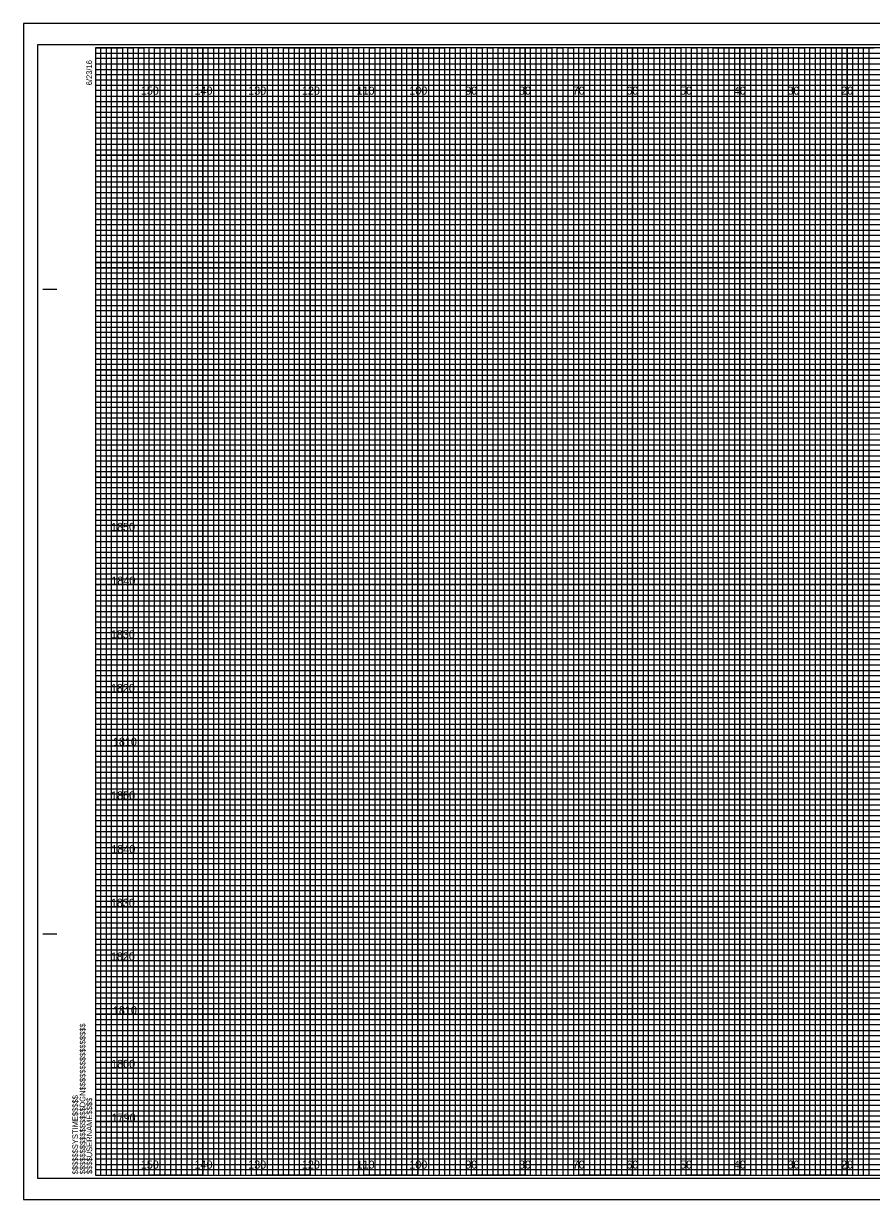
# Model space of a CAD drawing. Extents: x -13 to 323, y -5 to 874.
# Drawn here: x -13.4 to 144.5, y 655.5 to 874.5 of the extents above; entities that cross this region are included whole.
import ezdxf

# ---------------------------------------------------------------- set-up
doc = ezdxf.new("R2010")
doc.units = 0
for name, color, linetype in [('Prop XS Earthwork Shape', 7, 'Continuous'), ('Raster_Level_0', 7, 'Continuous'), ('Scratch_Level_3', 7, 'Continuous'), ('Sheet Cross Section CELL', 7, 'Continuous'), ('Sheet Cross Section Grid Middle CELL', 7, 'Continuous'), ('Sheet Cross Section Grid Minor 1 CELL', 7, 'Continuous'), ('Sheet Cross Section Grid Minor 2 CELL', 7, 'Continuous'), ('Sheet Cutting Line CELL', 7, 'Continuous'), ('Sheet DOT Grid CELL', 7, 'Continuous'), ('Sheet Plot Border Inside CELL', 7, 'Continuous'), ('Sheet Plot Border Outside CELL', 7, 'Continuous')]:
    doc.layers.add(name, color=color, linetype=linetype)

msp = doc.modelspace()

# ---------------------------------------------------------------- linework, layer by layer
at = {"layer": 'Prop XS Earthwork Shape'}
for p, q in [((10, 870), (0, 870)), ((10, 660), (10, 870)), ((30, 870), (20, 870)), ((20, 870), (20, 660)), ((30, 660), (30, 870)), ((50, 870), (40, 870)), ((40, 870), (40, 660)), ((50, 660), (50, 870)), ((70, 870), (60, 870)), ((60, 870), (60, 660)), ((70, 660), (70, 870)), ((90, 870), (80, 870)), ((80, 870), (80, 660)), ((90, 660), (90, 870)), ((110, 870), (100, 870)), ((100, 870), (100, 660)), ((110, 660), (110, 870)), ((130, 870), (120, 870)), ((120, 870), (120, 660)), ((130, 660), (130, 870)), ((150, 870), (140, 870)), ((140, 870), (140, 660)), ((20, 660), (10, 660)), ((40, 660), (30, 660)), ((60, 660), (50, 660)), ((80, 660), (70, 660)), ((100, 660), (90, 660)), ((120, 660), (110, 660)), ((140, 660), (130, 660))]:
    msp.add_line(p, q, dxfattribs=at)
for points in [[(0, 860), (320, 860), (320, 850), (0, 850)], [(0, 840), (320, 840), (320, 830), (0, 830)], [(0, 820), (320, 820), (320, 810), (0, 810)], [(0, 800), (320, 800), (320, 790), (0, 790)], [(0, 780), (320, 780), (320, 770), (0, 770)], [(0, 760), (320, 760), (320, 750), (0, 750)], [(0, 740), (320, 740), (320, 730), (0, 730)], [(0, 720), (320, 720), (320, 710), (0, 710)], [(0, 700), (320, 700), (320, 690), (0, 690)], [(0, 680), (320, 680), (320, 670), (0, 670)]]:
    msp.add_lwpolyline(points, dxfattribs=at)
at = {"layer": 'Sheet Cross Section CELL'}
for p, q in [((-9.8, 825), (-7.3, 825)), ((-9.7, 825), (-7.2, 825)), ((-9.8, 705), (-7.3, 705)), ((-9.7, 705), (-7.2, 705)), ((0, 660), (0, 660)), ((0, 660), (0, 660)), ((0, 660), (0, 660)), ((0, 660), (0, 660)), ((0, 660), (0, 660)), ((0, 660), (0, 660)), ((0, 660), (0, 660))]:
    msp.add_line(p, q, dxfattribs=at)
msp.add_lwpolyline([(320, 870), (0, 870), (0, 660), (320, 660)], close=True, dxfattribs=at)
at = {"layer": 'Sheet Cross Section Grid Middle CELL'}
for points in [[(0, 870), (5, 870), (5, 660), (15, 660), (15, 870), (25, 870), (25, 660), (35, 660), (35, 870), (45, 870), (45, 660), (55, 660), (55, 870), (65, 870), (65, 660), (75, 660), (75, 870), (85, 870), (85, 660), (95, 660), (95, 870), (105, 870), (105, 660), (115, 660), (115, 870), (125, 870), (125, 660), (135, 660), (135, 870), (145, 870)], [(0, 865), (275, 865)], [(0, 845), (320, 845), (320, 855), (0, 855)], [(0, 825), (320, 825), (320, 835), (0, 835)], [(0, 805), (320, 805), (320, 815), (0, 815)], [(0, 785), (320, 785), (320, 795), (0, 795)], [(0, 765), (320, 765), (320, 775), (0, 775)], [(0, 745), (320, 745), (320, 755), (0, 755)], [(0, 725), (320, 725), (320, 735), (0, 735)], [(0, 705), (320, 705), (320, 715), (0, 715)], [(0, 685), (320, 685), (320, 695), (0, 695)], [(0, 665), (320, 665), (320, 675), (0, 675)]]:
    msp.add_lwpolyline(points, dxfattribs=at)
at = {"layer": 'Sheet Cross Section Grid Minor 1 CELL'}
for p, q in [((0, 869), (260, 869)), ((260, 867.98), (0, 867.98)), ((0, 867.98), (0, 867)), ((0, 867), (260, 867)), ((260, 865.89), (0, 865.89)), ((0, 865.89), (0, 864)), ((0, 864), (320, 864))]:
    msp.add_line(p, q, dxfattribs=at)
for points in [[(0, 863), (270, 863), (320, 863), (320, 862), (0, 862)], [(0, 861), (320, 861), (320, 859), (0, 859)], [(0, 858), (320, 858), (320, 857), (0, 856.98)], [(0, 856), (320, 856), (320, 854), (0, 854)], [(0, 853), (320, 853), (320, 852), (0, 852)], [(0, 851), (320, 851), (320, 849), (0, 849)], [(0, 848), (320, 848), (320, 847), (0, 847)], [(0, 846), (320, 846), (320, 844), (0, 844)], [(0, 843), (320, 843), (320, 842), (0, 842)], [(0, 841), (320, 841), (320, 839), (0, 839)], [(0, 838), (320, 838), (320, 837), (0, 837)], [(0, 836), (320, 836), (320, 833.95), (320, 833), (320, 832), (0, 832)], [(0, 834), (320, 834), (320, 833), (0, 833)], [(0, 831), (320, 831), (320, 829), (0, 829.03)], [(0, 829.03), (320, 829), (320, 828), (0, 828)], [(0, 827), (320, 827), (320, 826), (0, 826)], [(0, 824), (320, 824), (320, 823), (0, 823)], [(0, 822), (320, 822), (320, 821), (0, 821)], [(-0.07, 818.89), (320, 818.89), (320, 817.88), (-0.07, 817.88)], [(0, 817), (320, 817), (320, 816), (0, 816)], [(0, 814), (320, 814), (320, 813), (0, 813)], [(0, 812), (320, 812), (320, 811), (0, 811)], [(0, 809), (320, 809), (320, 808), (0, 808)], [(0, 807), (320, 807), (320, 806), (0, 806)], [(0, 804), (320, 804), (320, 803), (0, 803)], [(0, 802), (320, 802), (320, 801), (0, 801)], [(0, 799), (320, 799), (319.99, 797.98), (0, 798)], [(0, 797), (320, 797), (320, 796), (0, 796)], [(0, 794), (320, 794), (320, 793), (0, 793)], [(0, 792), (320, 792), (320, 791), (0, 791)], [(0, 789), (320, 789), (320, 788), (0, 788)], [(0, 787), (320, 787), (320, 786), (0, 786)], [(0, 784), (320, 784), (320, 783), (0, 783)], [(0, 782), (320, 782), (320, 781), (0, 781)], [(0, 779), (320, 779), (320, 778), (0, 778)], [(0, 776.99), (320.07, 776.91), (320, 776), (0, 776)], [(0, 774), (320, 774), (320, 773), (0, 773)], [(0, 772), (320, 772), (320, 771), (0, 771)], [(0, 769), (320, 769), (320, 768), (0, 768)], [(0, 767), (320, 767), (320, 766), (0, 766)], [(0, 764), (320, 764), (320, 763), (0, 763)], [(0, 762), (320, 762), (320, 761), (0, 761)], [(0, 759), (320, 759), (320, 758), (0, 758)], [(0, 757), (320, 757), (320, 756), (0, 756)], [(0, 754), (320, 754), (320, 753), (0, 753)], [(0, 752), (320, 752), (320, 751), (0, 751)], [(0, 749), (320, 749), (320, 748), (0, 748)], [(0, 747), (320, 747), (320, 746), (0, 746)], [(0, 744), (320, 744), (320, 743), (0, 743)], [(0, 742), (320, 742), (320, 741), (0, 741)], [(0, 739), (320, 739), (319.99, 737.98), (0, 738)], [(0, 737), (320, 737), (320, 736), (0, 736)], [(0, 734), (320, 734), (320, 733), (0, 733)], [(0, 732), (320, 732), (320, 731), (0, 731)], [(0, 729), (320, 729), (320, 728), (0, 728)], [(0, 727), (320, 727), (320, 726), (0, 726)], [(0, 724), (320, 724), (320, 723), (0, 723)], [(0, 722), (320, 722), (320, 721), (0, 721)], [(0, 719), (320, 719), (320, 718), (0, 718)], [(0, 716.99), (320.07, 716.91), (320, 716), (0, 716)], [(0, 714), (320, 714), (320, 713), (0, 713)], [(0, 712), (320, 712), (320, 711), (0, 711)], [(0, 709), (320, 709), (320, 708), (0, 708)], [(0, 707), (320, 707), (320, 706), (0, 706)], [(0, 704), (320, 704), (320, 703), (0, 703)], [(0, 702), (320, 702), (320, 701), (0, 701)], [(0, 699), (320, 699), (320, 698), (0, 698)], [(0, 697), (320, 697), (320, 696), (0, 696)], [(0, 694), (320, 694), (320, 693), (0, 693)], [(0, 692), (320, 692), (320, 691), (0, 691)], [(0, 689), (320, 689), (320, 688), (0, 688)], [(0, 687), (320, 687), (320, 686), (0, 686)], [(0, 684), (320, 684), (320, 683), (0, 683)], [(0, 682), (320, 682), (320, 681), (0, 681)], [(0, 679), (320, 679), (320, 678), (0, 678)], [(0, 677), (320, 677), (320, 676), (0, 676)], [(0, 674), (320, 674), (320, 673), (0, 673)], [(0, 672), (320, 672), (320, 671), (0, 671)], [(0, 669), (320, 669), (320, 668), (0, 668)], [(0, 667), (320, 667), (320, 666), (0, 666)], [(0, 664), (320, 664), (320, 663), (0, 663)], [(0, 662), (320, 662), (320, 661), (0, 661)]]:
    msp.add_lwpolyline(points, dxfattribs=at)
at = {"layer": 'Sheet Cross Section Grid Minor 2 CELL'}
for points in [[(0, 660), (1, 660), (1, 870), (2, 870), (2, 660)], [(2, 660), (3, 660), (3, 870), (4, 870), (4, 660)], [(5, 660), (6, 660), (6, 870), (7, 870), (7, 660)], [(7, 660), (8, 660), (8, 870), (9, 870), (9, 660)], [(10, 660), (11, 660), (11, 870), (12, 870), (12, 660)], [(12, 660), (13, 660), (13, 870), (14, 870), (14, 660)], [(15, 660), (16, 660), (16, 870), (17, 870), (17, 660)], [(17, 660), (18, 660), (18, 870), (19, 870), (19, 660)], [(20, 660), (21, 660), (21, 870), (22, 870), (22, 660)], [(22, 660), (23, 660), (23, 870), (24, 870), (24, 660)], [(25, 660), (26, 660), (26, 870), (27, 870), (27, 660)], [(27, 660), (28, 660), (28, 870), (29, 870), (29, 660)], [(30, 660), (31, 660), (31, 870), (32, 870), (32, 660)], [(32, 660), (33, 660), (33, 870), (34, 870), (34, 660)], [(35, 660), (36, 660), (36, 870), (37, 870), (37, 660)], [(37, 660), (38, 660), (38, 870), (39, 870), (39, 660)], [(40, 660), (41, 660), (41, 870), (42, 870), (42, 660)], [(42, 660), (43, 660), (43, 870), (44, 870), (44, 660)], [(45, 660), (46, 660), (46, 870), (47, 870), (47, 660)], [(47, 660), (48, 660), (48, 870), (49, 870), (49, 660)], [(50, 660), (51, 660), (51, 870), (52, 870), (52, 660)], [(52, 660), (53, 660), (53, 870), (54, 870), (54, 660)], [(55, 660), (56, 660), (56, 870), (57, 870), (57, 660)], [(57, 660), (58, 660), (58, 870), (59, 870), (59, 660)], [(60, 660), (61, 660), (61, 870), (62, 870), (62, 660)], [(62, 660), (63, 660), (63, 870), (64, 870), (64, 660)], [(65, 660), (66, 660), (66, 870), (67, 870), (67, 660)], [(67, 660), (68, 660), (68, 870), (69, 870), (69, 660)], [(70, 660), (71, 660), (71, 870), (72, 870), (72, 660)], [(72, 660), (73, 660), (73, 870), (74, 870), (74, 660)], [(75, 660), (76, 660), (76, 870), (77, 870), (77, 660)], [(77, 660), (78, 660), (78, 870), (79, 870), (79, 660)], [(80, 660), (81, 660), (81, 870), (82, 870), (82, 660)], [(82, 660), (83, 660), (83, 870), (84, 870), (84, 660)], [(85, 660), (86, 660), (86, 870), (87, 870), (87, 660)], [(87, 660), (88, 660), (88, 870), (89, 870), (89, 660)], [(90, 660), (91, 660), (91, 870), (92, 870), (92, 660)], [(92, 660), (93, 660), (93, 870), (94, 870), (94, 660)], [(95, 660), (96, 660), (96, 870), (97, 870), (97, 660)], [(97, 660), (98, 660), (98, 870), (99, 870), (99, 660)], [(100, 660), (101, 660), (101, 870), (102, 870), (102, 660)], [(102, 660), (103, 660), (103, 870), (104, 870), (104, 660)], [(105, 660), (106, 660), (106, 870), (107, 870), (107, 660)], [(107, 660), (108, 660), (108, 870), (109, 870), (109, 660)], [(110, 660), (111, 660), (111, 870), (112, 870), (112, 660)], [(112, 660), (113, 660), (113, 870), (114, 870), (114, 660)], [(115, 660), (116, 660), (116, 870), (117, 870), (117, 660)], [(117, 660), (118, 660), (118, 870), (119, 870), (119, 660)], [(120, 660), (121, 660), (121, 870), (122, 870), (122, 660)], [(122, 660), (123, 660), (123, 870), (124, 870), (124, 660)], [(125, 660), (126, 660), (126, 870), (127, 870), (127, 660)], [(127, 660), (128, 660), (128, 870), (129, 870), (129, 660)], [(130, 660), (131, 660), (131, 870), (132, 870), (132, 660)], [(132, 660), (133, 660), (133, 870), (134, 870), (134, 660)], [(135, 660), (136, 660), (136, 870), (137, 870), (137, 660)], [(137, 660), (138, 660), (138, 870), (139, 870), (139, 660)], [(140, 660), (141, 660), (141, 870), (142, 870), (142, 660)], [(142, 660), (143, 660), (143, 870), (144, 870), (144, 660)]]:
    msp.add_lwpolyline(points, dxfattribs=at)
at = {"layer": 'Sheet Cutting Line CELL'}
for p, q in [((323.3, 874.5), (-13.4, 874.5)), ((-13.4, 874.5), (-13.4, 655.5)), ((-13.4, 655.5), (323.3, 655.5))]:
    msp.add_line(p, q, dxfattribs=at)
at = {"layer": 'Sheet DOT Grid CELL'}
for p, q in [((10, 660), (10, 870)), ((20, 660), (20, 870)), ((30, 660), (30, 870)), ((40, 660), (40, 870)), ((50, 660), (50, 870)), ((60, 660), (60, 870)), ((70, 660), (70, 870)), ((80, 660), (80, 870)), ((90, 660), (90, 870)), ((100, 660), (100, 870)), ((110, 660), (110, 870)), ((120, 660), (120, 870)), ((130, 660), (130, 870)), ((140, 660), (140, 870)), ((0, 860), (320, 860)), ((0, 850), (320, 850)), ((0, 840), (320, 840)), ((0, 830), (320, 830)), ((0, 820), (320, 820)), ((0, 810), (320, 810)), ((0, 800), (320, 800)), ((0, 790), (320, 790)), ((0, 780), (320, 780)), ((0, 770), (320, 770)), ((0, 760), (320, 760)), ((0, 750), (320, 750)), ((0, 740), (320, 740)), ((0, 730), (320, 730)), ((0, 720), (320, 720)), ((0, 710), (320, 710)), ((0, 700), (320, 700)), ((0, 690), (320, 690)), ((0, 680), (320, 680)), ((0, 670), (320, 670))]:
    msp.add_line(p, q, dxfattribs=at)
at = {"layer": 'Sheet Plot Border Inside CELL'}
msp.add_lwpolyline([(-10.8, 659.5), (322.4, 659.5), (322.4, 870.5), (-10.8, 870.5)], close=True, dxfattribs=at)
at = {"layer": 'Sheet Plot Border Outside CELL'}
msp.add_lwpolyline([(-13.4, 655.5), (323.3, 655.5), (323.3, 874.5), (-13.4, 874.5)], close=True, dxfattribs=at)

# ---------------------------------------------------------------- texts
at = {"layer": 'Raster_Level_0'}
for s, p in [('150', (8.44, 861.25)), ('140', (18.44, 861.25)), ('130', (28.44, 861.25)), ('120', (38.44, 861.25)), ('110', (48.62, 861.25)), ('100', (58.44, 861.25)), ('90', (68.86, 861.25)), ('80', (78.86, 861.25)), ('70', (88.86, 861.25)), ('60', (98.86, 861.25)), ('50', (108.86, 861.25)), ('40', (118.86, 861.25)), ('30', (128.86, 861.25)), ('20', (138.86, 861.25)), ('150', (8.44, 661.25)), ('140', (18.44, 661.25)), ('130', (28.44, 661.25)), ('120', (38.44, 661.25)), ('110', (48.62, 661.25)), ('100', (58.44, 661.25)), ('90', (68.86, 661.25)), ('80', (78.86, 661.25)), ('70', (88.86, 661.25)), ('60', (98.86, 661.25)), ('50', (108.86, 661.25)), ('40', (118.86, 661.25)), ('30', (128.86, 661.25)), ('20', (138.86, 661.25))]:
    msp.add_text(s, height=1.5, dxfattribs=at).set_placement(p)
at = {"layer": 'Scratch_Level_3'}
for s, p in [('1850', (2.9, 780)), ('1840', (2.95, 770)), ('1830', (2.86, 760)), ('1820', (2.87, 750)), ('1810', (3.25, 740)), ('1850', (2.9, 730)), ('1800', (2.92, 730)), ('1840', (2.95, 720)), ('1830', (2.86, 710)), ('1820', (2.87, 700)), ('1810', (3.25, 690)), ('1800', (2.92, 680)), ('1790', (3, 670))]:
    msp.add_text(s, height=1.5, dxfattribs=at).set_placement(p)
at = {"layer": 'Sheet Cross Section CELL'}
for s, p in [('6/23/16', (-0.65, 863)), ('$$$$$$$$$$$$$$$$DGN$$$$$$$$$$$$$$$$', (-1.88, 660.18)), ('$$$$$$SYSTIME$$$$$', (-3.26, 660.18)), ('$$$$USERNAME$$$$', (-0.62, 660.23))]:
    msp.add_text(s, height=1.05, rotation=90, dxfattribs=at).set_placement(p)

doc.saveas('drawing.dxf')
